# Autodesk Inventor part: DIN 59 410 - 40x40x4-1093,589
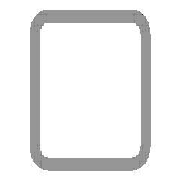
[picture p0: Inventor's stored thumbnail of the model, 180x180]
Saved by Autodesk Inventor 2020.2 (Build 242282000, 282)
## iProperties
Manager: www.cadconsulting.pl
Company: Fabian Stasiak CAD Consulting
IsCustomPart: 1
_CCFamilyMember: 20
_CCFamilyDisplayName: DIN 59410 (Kwadrat) - Rurki stalowe o przekroju kwadratowym formowane na gorąco
_FrameMemberDoc: Frame Member File
_Version: 15.0.0
_GetPNFromCC: 1
Created: 2015-01
Part Number: DIN 59 410 - 40x40x4-1093,589
Material: Stal, miękka
Description: Rurki stalowe o przekroju kwadratowym formowane na gorąco
Document SubType Name: Modellieren
Standard: DIN
Designer: F.Stasiak
Standards Organization: DIN
Language: pl-PL
Size Designation: 40x40x4
Categories: <MemberInstance><Categories><Category DisplayName="Kształtowniki konstrukcyjne" InternalName="089c4875-fa83-4c05-b084-43b9cc11f5ed" Mnemonic="GRDR"><CategoryPar
Stock Number: 40x40x4
Density: 7.85 g/cm^3
Appearance: Częściowo polerowana
Mass: 4393.44 g
Surface Area: 2813.5 cm^2
Volume: 559.674 cm^3
Catalog Web Link: www.expertbooks.pl
G_W: 40,000 mm
G_H: 40,000 mm
+0EF3C639-FB55-415C-9F0B-94C07BD3E324+CUTDETAIL1: Wytnij
+BFA23768-2E5A-4E03-B9C1-A7560C80BF1E+CUTDETAIL2: Wytnij
G_L: 1093,589 mm
Author: F.Stasiak
Subject: Zbiór ćwiczeń. Autodesk Inventor 2020. Kurs Professional
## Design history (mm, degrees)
node "Płaszczyzna początkowa"
node "Płaszczyzna końcowa"
sketch "Szkic1"
  geometry: L1 (-12, 20)-(12, 20); L2 (20, 12)-(20, -12); L3 (12, -20)-(-12, -20); L4 (-20, -12)-(-20, 12); L5 (-30.32, 0)-(30.32, 0) reference; L6 (0, -30.32)-(0, 30.32) reference; L7 (-12, 16)-(12, 16); L8 (16, 12)-(16, -12); L9 (12, -16)-(-12, -16); L10 (-16, -12)-(-16, 12); A1 r 8 centre (-12, 12) between (-12, 20) and (-20, 12); A2 r 8 centre (12, 12) between (20, 12) and (12, 20); A3 r 8 centre (12, -12) between (12, -20) and (20, -12); A4 r 8 centre (-12, -12) between (-20, -12) and (-12, -20); A5 r 4 centre (-12, 12) between (-12, 16) and (-16, 12); A6 r 4 centre (12, 12) between (16, 12) and (12, 16); A7 r 4 centre (12, -12) between (12, -16) and (16, -12); A8 r 4 centre (-12, -12) between (-16, -12) and (-12, -16); 3 further points
  constraints: 16 end point, 16 point on circle, 8 centre point, 8 tangent, 6 point on line, 4 parallel, 3 equal radius, 3 perpendicular, 1 horizontal, 7 other
  dimensions: "b" = 40 distance of point (-20, 20) point (20, 20); "msp_r" = 8 radius of A1 (= 2 x ParT); "d8" = 20 distance between parallel lines of L4 L6 (= d9); "d9" = 20 distance between parallel lines of L3 L5 (= 0.5 x b); "d10" = 4 distance between parallel lines of L3 L9 (= ParT)
extrude "Bryła" new body sketch "Szkic1" taper "d4" = 0 deg; stored distance "NLG" = 10
node "Driven Length"
  sketch "Sketch2"
    geometry: L1 (0, 0)-(10, 0) reference
    constraints: 2 end point, 1 horizontal
  workplane "Work Plane3"
  sketch "Sketch3"
    geometry: L1 (-2, 22.426)-(12, 22.426) reference; L2 (-2, 1116.016)-(12, 1116.016) reference
    dimensions: "d14" = 1093.5891 distance between parallel lines of L1 L2 (derived)
node "Płaszczyzna konstrukcyjna4"
feature "Podział1"
node "Płaszczyzna konstrukcyjna5"
feature "Podział2"
body "Solid1"
other parameters: "ParT" = 4, "G_OFFSET_START" = -22.42641 [user parameter; used in 1 equation term], "G_OFFSET_END" = -15.35534 [user parameter; used in 1 equation term], "d11" = 22.42641 (= -G_OFFSET_START), "d12" = 1116.01551 (= G_OFFSET_END + B_L), "G_L" = 1093.5891 (= d14) [user parameter], "B_L" = 1131.37085 [user parameter; used in 1 equation term], "d13" = 90 deg
